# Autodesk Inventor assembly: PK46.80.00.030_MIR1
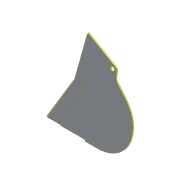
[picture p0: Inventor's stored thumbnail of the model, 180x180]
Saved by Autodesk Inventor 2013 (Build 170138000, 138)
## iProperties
Created: 2005-01
Part Number: PK46.80.00.030_MIR1
Document SubType Name: Assembly
Designer: hoeyj
Manufacturer: Standard
Standards Organization: Custom
Author: SAlex
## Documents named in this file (3)
- C:\Product Design Suite 2013 Test Drive\Dynamic Simulation\Workspace\Assy, Chassis, Front\PK46.80.00.030_MIR1.iam
- C:\Product Design Suite 2013 Test Drive\Dynamic Simulation\Workspace\Assy, Chassis, Front\PK46.80.00.017_MIR1.ipt
- C:\Product Design Suite 2013 Test Drive\Dynamic Simulation\Workspace\Assy, Chassis, Front\PK46.80.00.019_MIR1.ipt
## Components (2 placed, 2 different names)
1. PK46.80.00.017_MIR1:1 — Mate:2, Flush:1, Mate:1
2. PK46.80.00.019_MIR1:1 — Mate:2, Flush:1, Mate:1
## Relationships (3: Mate 2, Flush 1)
- Mate:2: PK46.80.00.017_MIR1:1 ↔ PK46.80.00.019_MIR1:1
- Flush:1: PK46.80.00.017_MIR1:1 ↔ PK46.80.00.019_MIR1:1
- Mate:1: PK46.80.00.017_MIR1:1 ↔ PK46.80.00.019_MIR1:1
